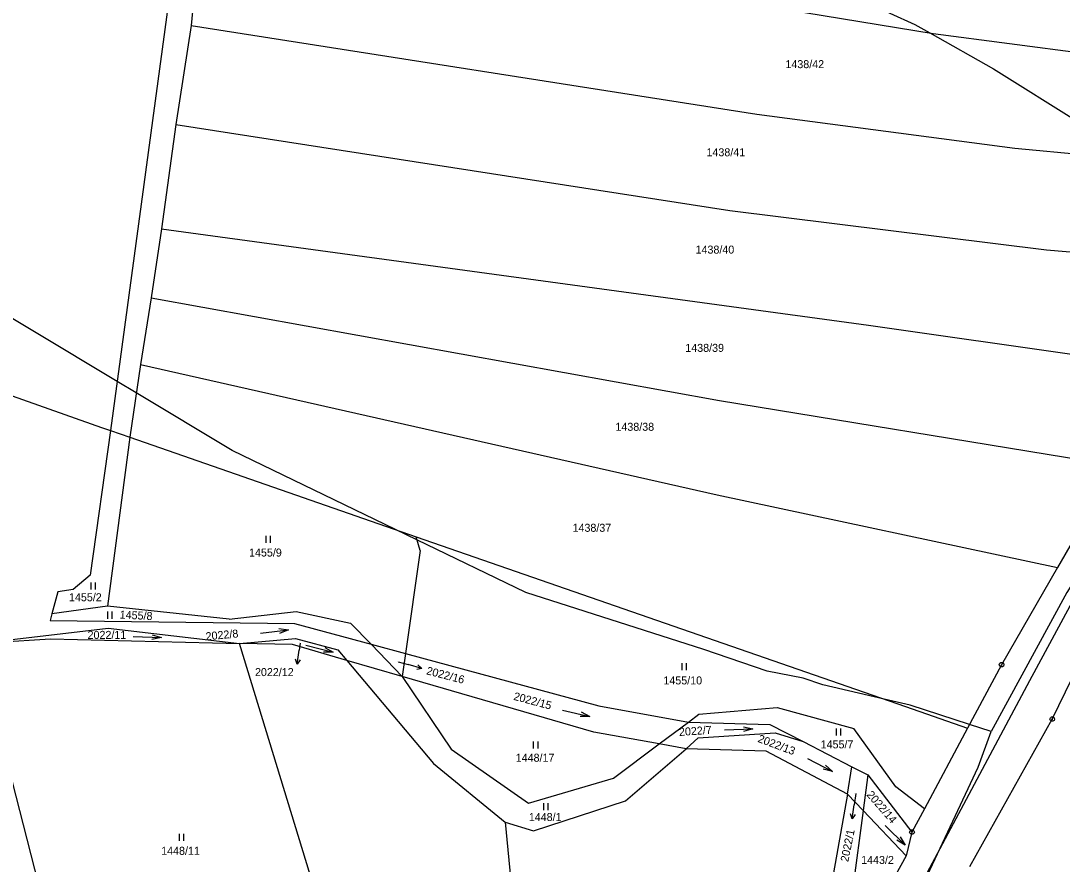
# Model space of a CAD drawing. Extents: x -789470 to -786707, y -1118640 to -1114455.
# Drawn here: x -787437 to -787215.8, y -1118466.7 to -1118287.5 of the extents above; entities that cross this region are included whole.
import ezdxf

# ---------------------------------------------------------------- set-up
doc = ezdxf.new("R2010")
doc.units = 0
for name, color, linetype in [('1', 7, 'Continuous'), ('11', 7, 'Continuous'), ('2', 7, 'Continuous'), ('3', 7, 'Continuous'), ('6', 7, 'Continuous'), ('7', 7, 'Continuous'), ('8', 7, 'Continuous')]:
    doc.layers.add(name, color=color, linetype=linetype)

msp = doc.modelspace()

# ---------------------------------------------------------------- linework, layer by layer
at = {"layer": '1'}
for p, q in [((-787402.57, -1118261.44), (-787417.9, -1118374.55)), ((-787398.59, -1118264.61), (-787400.74, -1118288.44)), ((-787398.59, -1118264.61), (-787243.13, -1118290.18)), ((-787400.74, -1118288.44), (-787404, -1118309.48)), ((-787400.74, -1118288.44), (-787280.62, -1118307.34)), ((-787243.13, -1118290.18), (-787160.15, -1118301.02)), ((-787280.62, -1118307.34), (-787225.85, -1118314.51)), ((-787404, -1118309.48), (-787407.09, -1118331.67)), ((-787404, -1118309.48), (-787286.38, -1118327.77)), ((-787225.85, -1118314.51), (-787170.53, -1118319.75)), ((-787286.38, -1118327.77), (-787219.07, -1118336.16)), ((-787407.09, -1118331.67), (-787409.24, -1118346.36)), ((-787407.09, -1118331.67), (-787256.87, -1118352.13)), ((-787219.07, -1118336.16), (-787181.11, -1118339.31)), ((-787409.24, -1118346.36), (-787411.56, -1118360.49)), ((-787409.24, -1118346.36), (-787288.56, -1118368.12)), ((-787256.87, -1118352.13), (-787192.93, -1118361.27)), ((-787411.56, -1118360.49), (-787413.8, -1118375.97)), ((-787411.56, -1118360.49), (-787289.04, -1118388.21)), ((-787438.82, -1118367.18), (-787419.84, -1118373.88)), ((-787288.56, -1118368.12), (-787204.45, -1118381.96)), ((-787419.84, -1118373.88), (-787417.9, -1118374.55)), ((-787417.9, -1118374.55), (-787422.24, -1118405.26)), ((-787413.8, -1118375.97), (-787418.52, -1118411.86)), ((-787417.9, -1118374.55), (-787413.8, -1118375.97)), ((-787413.8, -1118375.97), (-787353.01, -1118397.09)), ((-787289.04, -1118388.21), (-787216.75, -1118403.66)), ((-787209.71, -1118391.41), (-787216.75, -1118403.66)), ((-787352.13, -1118400.04), (-787353.01, -1118397.09)), ((-787353.01, -1118397.09), (-787249.07, -1118433.2)), ((-787217.86, -1118435.86), (-787198.68, -1118396.25)), ((-787352.13, -1118400.04), (-787355.26, -1118421.92)), ((-787216.75, -1118403.66), (-787228.62, -1118424.3)), ((-787422.24, -1118405.26), (-787425.81, -1118408.34)), ((-787429.1, -1118408.81), (-787430.33, -1118413.45)), ((-787425.81, -1118408.34), (-787429.1, -1118408.81)), ((-787430.33, -1118413.45), (-787430.71, -1118414.9)), ((-787418.52, -1118411.86), (-787430.33, -1118413.45)), ((-787392.73, -1118414.6), (-787418.52, -1118411.86)), ((-787392.73, -1118414.6), (-787378.48, -1118412.97)), ((-787378.48, -1118412.97), (-787366.89, -1118415.46)), ((-787430.71, -1118414.9), (-787378.79, -1118415.54)), ((-787378.79, -1118415.54), (-787362.57, -1118419.94)), ((-787366.89, -1118415.46), (-787362.57, -1118419.94)), ((-787445.72, -1118419.74), (-787418.4, -1118416.52)), ((-787418.4, -1118416.52), (-787390.51, -1118419.78)), ((-787445.72, -1118419.74), (-787430.63, -1118418.78)), ((-787430.63, -1118418.78), (-787390.51, -1118419.78)), ((-787390.51, -1118419.78), (-787378.63, -1118418.69)), ((-787362.53, -1118511.14), (-787390.51, -1118419.78)), ((-787379.27, -1118420.02), (-787390.51, -1118419.78)), ((-787367.67, -1118423.39), (-787379.27, -1118420.02)), ((-787378.63, -1118418.69), (-787369.58, -1118421.11)), ((-787362.57, -1118419.94), (-787355.96, -1118426.79)), ((-787362.57, -1118419.94), (-787355.26, -1118421.92)), ((-787369.58, -1118421.11), (-787367.67, -1118423.39)), ((-787355.26, -1118421.92), (-787355.96, -1118426.79)), ((-787355.26, -1118421.92), (-787314.2, -1118433.05)), ((-787367.67, -1118423.39), (-787349.3, -1118445.29)), ((-787355.96, -1118426.79), (-787367.67, -1118423.39)), ((-787228.62, -1118424.3), (-787235.84, -1118437.8)), ((-787355.96, -1118426.79), (-787345.51, -1118442.25)), ((-787315.26, -1118438.6), (-787355.96, -1118426.79)), ((-787433.19, -1118470.77), (-787443.96, -1118428.82)), ((-787314.2, -1118433.05), (-787295.11, -1118436.5)), ((-787292.97, -1118434.78), (-787276.27, -1118433.38)), ((-787276.27, -1118433.38), (-787260.01, -1118437.85)), ((-787249.07, -1118433.2), (-787235.84, -1118437.8)), ((-787295.11, -1118436.5), (-787292.97, -1118434.78)), ((-787235.39, -1118467.18), (-787217.86, -1118435.86)), ((-787301.35, -1118441.14), (-787295.11, -1118436.5)), ((-787295.11, -1118436.5), (-787277.84, -1118436.97)), ((-787277.84, -1118436.97), (-787270.8, -1118440.61)), ((-787251.12, -1118450.22), (-787260.01, -1118437.85)), ((-787235.84, -1118437.8), (-787245.01, -1118454.92)), ((-787301.35, -1118441.14), (-787315.26, -1118438.6)), ((-787295.65, -1118442.18), (-787293.11, -1118439.81)), ((-787293.11, -1118439.81), (-787276.71, -1118438.78)), ((-787276.71, -1118438.78), (-787270.8, -1118440.61)), ((-787345.51, -1118442.25), (-787329.12, -1118453.71)), ((-787311.09, -1118448.38), (-787301.35, -1118441.14)), ((-787308.54, -1118453.2), (-787295.65, -1118442.18)), ((-787295.65, -1118442.18), (-787301.35, -1118441.14)), ((-787278.62, -1118442.65), (-787295.65, -1118442.18)), ((-787270.8, -1118440.61), (-787260.47, -1118445.96)), ((-787261.35, -1118451.77), (-787278.62, -1118442.65)), ((-787349.3, -1118445.29), (-787334.09, -1118457.75)), ((-787261.35, -1118451.77), (-787260.47, -1118445.96)), ((-787260.47, -1118445.96), (-787257.07, -1118447.72)), ((-787329.12, -1118453.71), (-787311.09, -1118448.38)), ((-787257.07, -1118447.72), (-787258.06, -1118455.25)), ((-787257.07, -1118447.72), (-787247.66, -1118459.87)), ((-787245.01, -1118454.92), (-787251.12, -1118450.22)), ((-787328.03, -1118459.56), (-787308.54, -1118453.2)), ((-787261.35, -1118451.77), (-787270.69, -1118504.24)), ((-787258.06, -1118455.25), (-787261.35, -1118451.77)), ((-787258.06, -1118455.25), (-787262.52, -1118489.37)), ((-787248.91, -1118464.91), (-787258.06, -1118455.25)), ((-787245.01, -1118454.92), (-787247.66, -1118459.87)), ((-787334.09, -1118457.75), (-787328.03, -1118459.56)), ((-787334.09, -1118457.75), (-787329.35, -1118506.42)), ((-787247.66, -1118459.87), (-787248.91, -1118464.91)), ((-787248.91, -1118464.91), (-787260.38, -1118485.47))]:
    msp.add_line(p, q, dxfattribs=at)
at = {"layer": '11'}
for points in [[(-787316.1, -1118256.91), (-787247.04, -1118288.28), (-787243.88, -1118290.06), (-787230.33, -1118297.66), (-787211.99, -1118309.19), (-787198.67, -1118317.08), (-787181.95, -1118326.99), (-787176.94, -1118331.46), (-787176.56, -1118331.8), (-787175.02, -1118337.35), (-787175.54, -1118340.72), (-787178.69, -1118347.39), (-787189.28, -1118362.31), (-787193.8, -1118372.33), (-787200.96, -1118385.66), (-787205.43, -1118393.99), (-787214.75, -1118408.94), (-787230.84, -1118438.51)], [(-787230.84, -1118438.51), (-787235.42, -1118437.02), (-787248.07, -1118432.92), (-787253.59, -1118431.63), (-787266.61, -1118428.57), (-787270.81, -1118427.18), (-787278.41, -1118425.69), (-787291.85, -1118421.07), (-787329.69, -1118408.96), (-787352.8, -1118397.78), (-787357.34, -1118395.58), (-787392.05, -1118378.79), (-787412.44, -1118366.55), (-787416.49, -1118364.12), (-787451.29, -1118343.22), (-787466.78, -1118336), (-787500, -1118332.13), (-787500.74, -1118332.04), (-787514.34, -1118330.63), (-787515.61, -1118330.5)], [(-787255.68, -1118493.19), (-787233.59, -1118446.04), (-787230.84, -1118438.51)]]:
    msp.add_lwpolyline(points, dxfattribs=at)
at = {"layer": '3'}
for p, q in [((-787384.9, -1118396.91), (-787384.9, -1118398.41)), ((-787383.9, -1118398.41), (-787383.9, -1118396.91)), ((-787422.08, -1118406.81), (-787422.08, -1118408.31)), ((-787421.08, -1118408.31), (-787421.08, -1118406.81)), ((-787418.53, -1118413.02), (-787418.53, -1118414.52)), ((-787417.53, -1118414.52), (-787417.53, -1118413.02)), ((-787386.07, -1118417.61), (-787380.12, -1118416.89)), ((-787413.09, -1118418.31), (-787407.09, -1118418.53)), ((-787376.4, -1118420.11), (-787370.6, -1118421.61)), ((-787296.54, -1118423.95), (-787296.54, -1118425.45)), ((-787295.54, -1118425.45), (-787295.54, -1118423.95)), ((-787321.91, -1118433.93), (-787316.07, -1118435.27)), ((-787287.45, -1118438.11), (-787281.45, -1118437.91)), ((-787263.77, -1118437.83), (-787263.77, -1118439.33)), ((-787262.77, -1118439.33), (-787262.77, -1118437.83)), ((-787328.09, -1118440.62), (-787328.09, -1118442.12)), ((-787327.09, -1118442.12), (-787327.09, -1118440.62)), ((-787269.83, -1118444.22), (-787264.51, -1118447)), ((-787325.94, -1118453.72), (-787325.94, -1118455.22)), ((-787324.94, -1118455.22), (-787324.94, -1118453.72)), ((-787403.33, -1118460.21), (-787403.33, -1118461.71)), ((-787402.33, -1118461.71), (-787402.33, -1118460.21)), ((-787253.39, -1118458.46), (-787249.09, -1118462.64))]:
    msp.add_line(p, q, dxfattribs=at)
for points in [[(-787409.07, -1118417.96), (-787407.09, -1118418.53), (-787409.11, -1118418.96)], [(-787382.16, -1118416.63), (-787380.12, -1118416.89), (-787382.04, -1118417.63)], [(-787372.41, -1118420.63), (-787370.6, -1118421.61), (-787372.66, -1118421.6)], [(-787317.9, -1118434.34), (-787316.07, -1118435.27), (-787318.13, -1118435.31)], [(-787283.47, -1118437.48), (-787281.45, -1118437.91), (-787283.43, -1118438.48)], [(-787266.05, -1118445.63), (-787264.51, -1118447), (-787266.51, -1118446.52)], [(-787250.17, -1118460.89), (-787249.09, -1118462.64), (-787250.87, -1118461.61)]]:
    msp.add_lwpolyline(points, dxfattribs=at)
at = {"layer": '6'}
for p, q in [((-787222.61, -1118427.68), (-787204.25, -1118393.43)), ((-787319.31, -1118608.45), (-787222.61, -1118427.68))]:
    msp.add_line(p, q, dxfattribs=at)
at = {"layer": '7'}
for p, q in [((-787377.64, -1118419.7), (-787377.85, -1118421.18)), ((-787378.28, -1118424.15), (-787377.85, -1118421.18)), ((-787356.79, -1118423.68), (-787354.66, -1118424.28)), ((-787351.77, -1118425.1), (-787354.66, -1118424.28)), ((-787259.61, -1118451.64), (-787259.94, -1118454.06)), ((-787260.35, -1118457.03), (-787259.94, -1118454.06))]:
    msp.add_line(p, q, dxfattribs=at)
for points in [[(-787377.64, -1118423.23), (-787378.28, -1118424.15), (-787378.63, -1118423.09)], [(-787352.6, -1118424.34), (-787351.77, -1118425.1), (-787352.87, -1118425.31)], [(-787259.72, -1118456.11), (-787260.35, -1118457.03), (-787260.71, -1118455.97)]]:
    msp.add_lwpolyline(points, dxfattribs=at)
at = {"layer": '8'}
for p, q in [((-787228.74, -1118424.3), (-787228.5, -1118424.3)), ((-787217.98, -1118435.86), (-787217.74, -1118435.86)), ((-787247.78, -1118459.87), (-787247.54, -1118459.87))]:
    msp.add_line(p, q, dxfattribs=at)
for points in [[(-787228.47, -1118423.82), (-787228.22, -1118424), (-787228.12, -1118424.29), (-787228.22, -1118424.58), (-787228.47, -1118424.76), (-787228.78, -1118424.76), (-787229.03, -1118424.58), (-787229.13, -1118424.29), (-787229.03, -1118424), (-787228.78, -1118423.82)], [(-787217.71, -1118435.38), (-787217.46, -1118435.56), (-787217.36, -1118435.85), (-787217.46, -1118436.14), (-787217.71, -1118436.32), (-787218.02, -1118436.32), (-787218.27, -1118436.14), (-787218.37, -1118435.85), (-787218.27, -1118435.56), (-787218.02, -1118435.38)], [(-787247.51, -1118459.39), (-787247.26, -1118459.57), (-787247.16, -1118459.86), (-787247.26, -1118460.15), (-787247.51, -1118460.33), (-787247.82, -1118460.33), (-787248.07, -1118460.15), (-787248.17, -1118459.86), (-787248.07, -1118459.57), (-787247.82, -1118459.39)]]:
    msp.add_lwpolyline(points, close=True, dxfattribs=at)

# ---------------------------------------------------------------- texts
at = {"layer": '2'}
for s, height, p in [('1438/42', 1.7, (-787274.54, -1118297.54)), ('1438/41', 1.7, (-787291.31, -1118316.26)), ('1438/40', 1.7, (-787293.63, -1118336.94)), ('1438/39', 1.7, (-787295.81, -1118357.82)), ('1438/38', 1.7, (-787310.65, -1118374.59)), ('1438/37', 1.7, (-787319.76, -1118396.05)), ('1455/9', 1.7, (-787388.47, -1118401.31)), ('1455/2', 1.7, (-787426.72, -1118410.81)), ('2022/11', 1.7, (-787422.77, -1118418.81)), ('2022/12', 0.1, (-787377.92, -1118419.7)), ('2022/16', 0.1, (-787357.07, -1118423.68)), ('1455/10', 1.7, (-787300.46, -1118428.48)), ('1455/7', 1.7, (-787267.06, -1118442.07)), ('1448/17', 1.7, (-787331.83, -1118444.91)), ('2022/1', 0.1, (-787259.85, -1118451.64)), ('1448/1', 1.7, (-787329.05, -1118457.51)), ('1448/11', 1.7, (-787407.14, -1118464.69)), ('1443/2', 1.7, (-787258.46, -1118466.63))]:
    msp.add_text(s, height=height, dxfattribs=at).set_placement(p)
for s, rotation, p in [('1455/8', 357.2965, (-787415.98, -1118414.49)), ('2022/8', 5.3858, (-787397.61, -1118419.13)), ('2022/15', 344.9779, (-787332.42, -1118431.72)), ('2022/7', 3.8961, (-787297.09, -1118439.44)), ('2022/13', 339.5348, (-787280.56, -1118440.66)), ('2022/14', 311.1161, (-787257.42, -1118451.99))]:
    msp.add_text(s, height=1.7, rotation=rotation, dxfattribs=at).set_placement(p)
at = {"layer": '7'}
for s, rotation, p in [('2022/16', 345.4936, (-787350.93, -1118426.3)), ('2022/1', 78.4379, (-787261.21, -1118466.29))]:
    msp.add_text(s, height=1.7, rotation=rotation, dxfattribs=at).set_placement(p)
msp.add_text('2022/12', height=1.7, dxfattribs=at).set_placement((-787387.21, -1118426.71))

doc.saveas('drawing.dxf')
